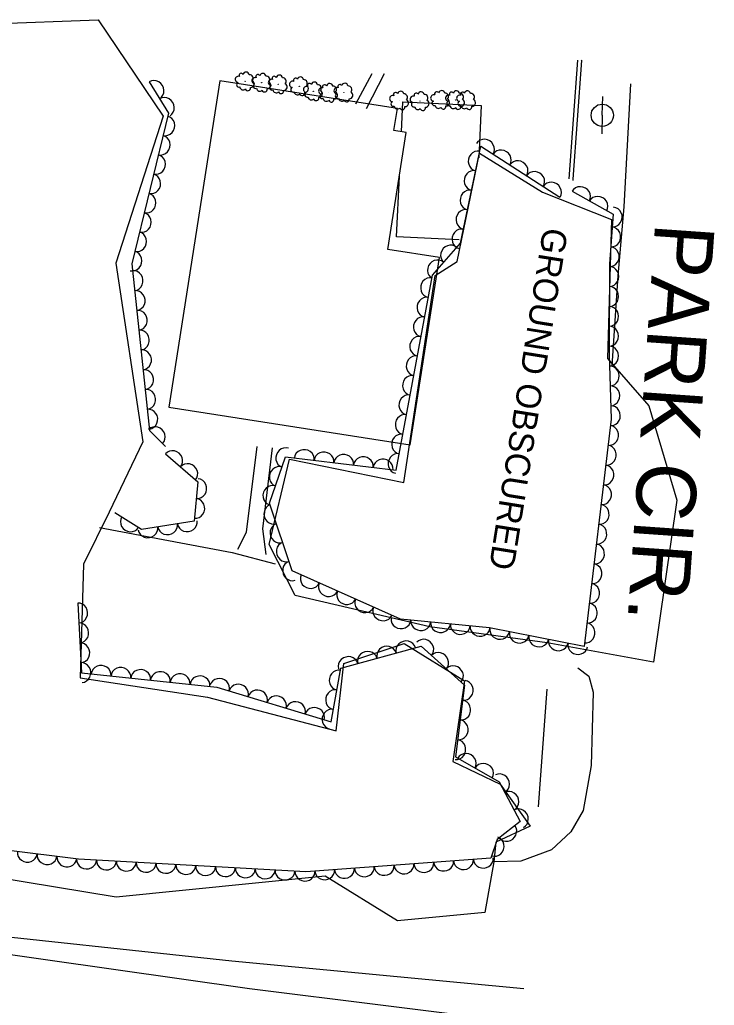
# Model space of a CAD drawing. Extents: x 1722896 to 1754269, y 648279 to 666297.
# Drawn here: x 1725117.8 to 1725257.5, y 658648.9 to 658847.2 of the extents above; entities that cross this region are included whole.
import ezdxf

# ---------------------------------------------------------------- set-up
doc = ezdxf.new("R2010")
doc.units = 0
for name, color, linetype in [('DESIGN - CENTERLINE - Proposed Text', 7, 'Continuous'), ('DESIGN - SHEET - Linework', 7, 'Continuous'), ('SURVEY - CENTERLINE - Preliminary', 7, 'Continuous'), ('SURVEY - CENTERLINE - Preliminary Text', 7, 'Continuous'), ('SURVEY - DTM - Breaklines', 7, 'Continuous'), ('SURVEY - VEGETATION - Features with Text', 7, 'Continuous')]:
    doc.layers.add(name, color=color, linetype=linetype)

msp = doc.modelspace()

# ---------------------------------------------------------------- linework, layer by layer
at = {"layer": 'DESIGN - CENTERLINE - Proposed Text'}
for points in [[(1725229.98, 658839.02), (1725228.27, 658815.18)], [(1725230.8, 658838.94), (1725229.09, 658815.1)], [(1725230.76, 658838.94), (1725230.81, 658839.01)], [(1725230.81, 658839.01), (1725230.8, 658838.94)], [(1725185.38, 658830.26), (1725188.67, 658836.35)], [(1725187.56, 658829.3), (1725191.15, 658836.34)], [(1725194.59, 658824.63), (1725194.88, 658830.65), (1725210.64, 658829.88), (1725210.13, 658819.39)], [(1725206.17, 658802.85), (1725193.55, 658803.47), (1725194.15, 658815.67)], [(1725229.09, 658815.1), (1725229.07, 658814.78)], [(1725161.62, 658740.64), (1725163.4, 658744.08), (1725165.56, 658761.33)], [(1725167.35, 658739.54), (1725166.68, 658744.73), (1725168.6, 658761.05)]]:
    msp.add_lwpolyline(points, dxfattribs=at)
msp.add_lwpolyline([(1725158, 658834.87), (1725147.74, 658769.2), (1725196.31, 658761.6), (1725202.2, 658799.32), (1725191.85, 658800.94), (1725195.53, 658824.49), (1725193.06, 658824.87), (1725193.75, 658829.28)], close=True, dxfattribs=at)
at = {"layer": 'SURVEY - CENTERLINE - Preliminary'}
for points in [[(1725111.82, 658846.36), (1725133.57, 658847.16), (1725146.63, 658827.76), (1725137.09, 658798.19), (1725142.5, 658762.21), (1725135.77, 658748.1), (1725130.6, 658737.62), (1725129.93, 658714.73), (1725155.55, 658710.84), (1725181.46, 658704.07), (1725182.96, 658717.62), (1725195.12, 658721.67), (1725207.28, 658714.18), (1725204.92, 658697.92), (1725214.43, 658693.35)], [(1725210.29, 658820.28), (1725222.98, 658812.44), (1725236.82, 658806.95), (1725236.04, 658778.97), (1725244.35, 658769.51), (1725249.96, 658750.49), (1725245.31, 658717.93), (1725223.89, 658721.79), (1725200.31, 658725), (1725173.17, 658731.31), (1725167.97, 658741.56), (1725172.06, 658758.72), (1725195.05, 658754.06), (1725201.37, 658795.7), (1725205.79, 658798.51), (1725210.29, 658820.28)], [(1725214.43, 658693.35), (1725220.49, 658684.94), (1725213.59, 658681.71), (1725213.18, 658677.77), (1725211.34, 658667.52), (1725193.77, 658665.88), (1725179.24, 658674.83), (1725137.19, 658670.6), (1725112.71, 658674.62)]]:
    msp.add_lwpolyline(points, dxfattribs=at)
at = {"layer": 'SURVEY - CENTERLINE - Preliminary Text'}
for points in [[(1725240.69, 658834.23), (1725239.33, 658809.49), (1725238.11, 658795.64), (1725236.92, 658777.55)], [(1725133.84, 658744.99), (1725160.51, 658739.96), (1725169.16, 658737.69)], [(1725230.1, 658716.75), (1725232.28, 658715.06), (1725233.14, 658711.9), (1725232.73, 658697.1), (1725231.11, 658688.08), (1725228.64, 658683.77), (1725224.75, 658680.18), (1725218.58, 658677.88), (1725213.18, 658677.77)], [(1725219.21, 658652.2), (1725160.44, 658657.78), (1725101.71, 658664.08), (1725041.61, 658671.16), (1725000.01, 658674.94), (1724971.97, 658677.19)], [(1725000.01, 658674.94), (1725035.79, 658669.37), (1725077.62, 658663.58), (1725109.21, 658660.02), (1725163.97, 658652.27), (1725217.78, 658645.58)]]:
    msp.add_lwpolyline(points, dxfattribs=at)
at = {"layer": 'SURVEY - DTM - Breaklines'}
for q in [(1725235.09, 658831.68), (1725234.9, 658824.18)]:
    msp.add_line((1725234.99, 658827.93), q, dxfattribs=at)
msp.add_circle((1725234.99, 658827.93), 2.25, dxfattribs=at)
at = {"layer": 'SURVEY - VEGETATION - Features with Text'}
for points in [[(1725143.81, 658834.65), (1725147.68, 658828.36), (1725140.32, 658798.03), (1725143.89, 658764.51), (1725147.1, 658761.32)], [(1725228.92, 658812.64), (1725237.15, 658808.03), (1725236.42, 658798.02), (1725236.38, 658779.8), (1725236.76, 658766.83), (1725231.31, 658721.09), (1725212.28, 658724.8), (1725194.41, 658726.54), (1725172.56, 658736.27), (1725168.05, 658749.91), (1725171.25, 658759.24), (1725193.52, 658756.54), (1725200.8, 658795.79), (1725206.46, 658802.21), (1725210.53, 658821.71), (1725226.46, 658811.48)], [(1725147.09, 658759.82), (1725153.62, 658754.19), (1725152.87, 658746.28), (1725142.27, 658744.63), (1725136.92, 658747.98)], [(1725129.42, 658729.79), (1725130.18, 658715.79), (1725157.44, 658712.9), (1725180.4, 658705.88), (1725182.38, 658716.73), (1725198.53, 658721.12), (1725207.25, 658713.31), (1725205.45, 658698.88), (1725214.22, 658693.86), (1725218.48, 658685.88), (1725213.81, 658682.2), (1725212.54, 658678.47), (1725175.33, 658675.74), (1725129.59, 658678.29), (1725100.41, 658681.89), (1725079.83, 658690.36), (1725046.88, 658695.34), (1725023.57, 658703), (1725006.03, 658707.8), (1725000.3, 658699.63), (1724944.71, 658706.84), (1724923.46, 658711.67), (1724891.95, 658713.84), (1724888, 658725.66)], [(1725223.84, 658712.46), (1725222.06, 658688.83)]]:
    msp.add_lwpolyline(points, dxfattribs=at)
for centre in [(1725163.11, 658834.76), (1725166.46, 658834.5), (1725169.78, 658834.16), (1725174.03, 658833.77), (1725176.85, 658832.74), (1725179.9, 658832.46), (1725182.98, 658832.49), (1725194.19, 658830.9), (1725198.3, 658830.78), (1725202.44, 658831.04), (1725205.43, 658830.99), (1725207.66, 658830.98)]:
    msp.add_circle(centre, 0.022, dxfattribs=at)
for centre, radius, start, end in [((1725161.75, 658835.15), 0.629, 70.277, 263.6967), ((1725162.34, 658835.95), 0.433, 30.2563, 209.002), ((1725163.32, 658836), 0.631, 8.1402, 164.9291), ((1725164.01, 658835.38), 0.719, 317.1929, 94.7171), ((1725165.1, 658834.88), 0.629, 70.277, 263.6967), ((1725165.69, 658835.69), 0.433, 30.2563, 209.002), ((1725166.68, 658835.74), 0.631, 8.1402, 164.9291), ((1725167.36, 658835.12), 0.719, 317.1929, 94.7171), ((1725169, 658835.35), 0.433, 30.2563, 209.002), ((1725169.99, 658835.4), 0.631, 8.1402, 164.9291), ((1725170.67, 658834.78), 0.719, 317.1929, 94.7171), ((1725174.24, 658835.01), 0.631, 8.1402, 164.9291), ((1725161.87, 658834.08), 0.479, 112.8957, 290.2148), ((1725162.7, 658833.73), 0.679, 188.1827, 315.0284), ((1725163.68, 658833.41), 0.527, 198.3416, 13.3419), ((1725164.22, 658834.25), 0.714, 268.0887, 63.9272), ((1725165.22, 658833.82), 0.479, 112.8957, 290.2148), ((1725167.57, 658833.99), 0.714, 268.0887, 63.9272), ((1725168.41, 658834.55), 0.629, 70.277, 263.6967), ((1725168.53, 658833.48), 0.479, 112.8957, 290.2148), ((1725170.88, 658833.65), 0.714, 268.0887, 63.9272), ((1725172.67, 658834.16), 0.629, 70.277, 263.6967), ((1725172.78, 658833.09), 0.479, 112.8957, 290.2148), ((1725173.26, 658834.96), 0.433, 30.2563, 209.002), ((1725175.48, 658833.13), 0.629, 70.277, 263.6967), ((1725174.92, 658834.39), 0.719, 317.1929, 94.7171), ((1725175.14, 658833.26), 0.714, 268.0887, 63.9272), ((1725176.08, 658833.93), 0.433, 30.2563, 209.002), ((1725177.06, 658833.99), 0.631, 8.1402, 164.9291), ((1725177.74, 658833.36), 0.719, 317.1929, 94.7171), ((1725179.12, 658833.65), 0.433, 30.2563, 209.002), ((1725180.11, 658833.7), 0.631, 8.1402, 164.9291), ((1725180.79, 658833.08), 0.719, 317.1929, 94.7171), ((1725181.62, 658832.88), 0.629, 70.277, 263.6967), ((1725182.21, 658833.68), 0.433, 30.2563, 209.002), ((1725183.19, 658833.74), 0.631, 8.1402, 164.9291), ((1725183.88, 658833.11), 0.719, 317.1929, 94.7171), ((1725166.06, 658833.46), 0.679, 188.1827, 315.0284), ((1725167.04, 658833.15), 0.527, 198.3416, 13.3419), ((1725169.37, 658833.13), 0.679, 188.1827, 315.0284), ((1725170.35, 658832.81), 0.527, 198.3416, 13.3419), ((1725173.62, 658832.74), 0.679, 188.1827, 315.0284), ((1725174.6, 658832.42), 0.527, 198.3416, 13.3419), ((1725175.6, 658832.06), 0.479, 112.8957, 290.2148), ((1725176.44, 658831.71), 0.679, 188.1827, 315.0284), ((1725177.42, 658831.4), 0.527, 198.3416, 13.3419), ((1725178.53, 658832.84), 0.629, 70.277, 263.6967), ((1725177.95, 658832.23), 0.714, 268.0887, 63.9272), ((1725178.65, 658831.78), 0.479, 112.8957, 290.2148), ((1725181, 658831.95), 0.714, 268.0887, 63.9272), ((1725181.74, 658831.81), 0.479, 112.8957, 290.2148), ((1725184.09, 658831.98), 0.714, 268.0887, 63.9272), ((1725192.82, 658831.29), 0.629, 70.277, 263.6967), ((1725193.41, 658832.09), 0.433, 30.2563, 209.002), ((1725194.4, 658832.14), 0.631, 8.1402, 164.9291), ((1725195.08, 658831.52), 0.719, 317.1929, 94.7171), ((1725196.94, 658831.17), 0.629, 70.277, 263.6967), ((1725197.53, 658831.97), 0.433, 30.2563, 209.002), ((1725198.51, 658832.02), 0.631, 8.1402, 164.9291), ((1725199.2, 658831.4), 0.719, 317.1929, 94.7171), ((1725201.08, 658831.43), 0.629, 70.277, 263.6967), ((1725201.67, 658832.23), 0.433, 30.2563, 209.002), ((1725202.65, 658832.28), 0.631, 8.1402, 164.9291), ((1725203.34, 658831.66), 0.719, 317.1929, 94.7171), ((1725204.07, 658831.37), 0.629, 70.277, 263.6967), ((1725204.66, 658832.18), 0.433, 30.2563, 209.002), ((1725205.64, 658832.23), 0.631, 8.1402, 164.9291), ((1725206.3, 658831.36), 0.629, 70.277, 263.6967), ((1725206.32, 658831.61), 0.719, 317.1929, 94.7171), ((1725206.89, 658832.16), 0.433, 30.2563, 209.002), ((1725207.87, 658832.22), 0.631, 8.1402, 164.9291), ((1725208.55, 658831.59), 0.719, 317.1929, 94.7171), ((1725179.49, 658831.42), 0.679, 188.1827, 315.0284), ((1725180.47, 658831.11), 0.527, 198.3416, 13.3419), ((1725182.57, 658831.46), 0.679, 188.1827, 315.0284), ((1725183.55, 658831.15), 0.527, 198.3416, 13.3419), ((1725192.94, 658830.22), 0.479, 112.8957, 290.2148), ((1725193.78, 658829.87), 0.679, 188.1827, 315.0284), ((1725194.76, 658829.55), 0.527, 198.3416, 13.3419), ((1725195.29, 658830.39), 0.714, 268.0887, 63.9272), ((1725197.06, 658830.1), 0.479, 112.8957, 290.2148), ((1725197.89, 658829.75), 0.679, 188.1827, 315.0284), ((1725198.87, 658829.43), 0.527, 198.3416, 13.3419), ((1725199.41, 658830.27), 0.714, 268.0887, 63.9272), ((1725201.2, 658830.36), 0.479, 112.8957, 290.2148), ((1725202.03, 658830.01), 0.679, 188.1827, 315.0284), ((1725203.01, 658829.69), 0.527, 198.3416, 13.3419), ((1725203.55, 658830.53), 0.714, 268.0887, 63.9272), ((1725204.18, 658830.31), 0.479, 112.8957, 290.2148), ((1725205.02, 658829.95), 0.679, 188.1827, 315.0284), ((1725206, 658829.64), 0.527, 198.3416, 13.3419), ((1725206.41, 658830.3), 0.479, 112.8957, 290.2148), ((1725206.54, 658830.48), 0.714, 268.0887, 63.9272), ((1725207.25, 658829.94), 0.679, 188.1827, 315.0284), ((1725208.23, 658829.63), 0.527, 198.3416, 13.3419), ((1725208.77, 658830.46), 0.714, 268.0887, 63.9272)]:
    msp.add_arc(centre, radius, start, end, dxfattribs=at)
for centre, major_axis in [((1725144.86, 658832.95), (1.05, -1.7)), ((1725146.95, 658829.54), (1.05, -1.7)), ((1725147.06, 658825.82), (-0.47, -1.94)), ((1725146.12, 658821.93), (-0.47, -1.94)), ((1725211.33, 658821.19), (1.68, -1.08)), ((1725145.18, 658818.05), (-0.47, -1.94)), ((1725209.91, 658818.73), (0.41, 1.96)), ((1725214.7, 658819.03), (1.68, -1.08)), ((1725218.07, 658816.87), (1.68, -1.08)), ((1725144.23, 658814.16), (-0.47, -1.94)), ((1725209.09, 658814.81), (0.41, 1.96)), ((1725221.43, 658814.7), (1.68, -1.08)), ((1725224.8, 658812.54), (1.68, -1.08)), ((1725230.66, 658811.66), (1.74, -0.98)), ((1725143.29, 658810.27), (-0.47, -1.94)), ((1725208.27, 658810.9), (0.41, 1.96)), ((1725234.15, 658809.71), (1.74, -0.98)), ((1725142.35, 658806.38), (-0.47, -1.94)), ((1725207.45, 658806.98), (0.41, 1.96)), ((1725237.11, 658807.46), (-0.15, -1.99)), ((1725141.4, 658802.5), (-0.47, -1.94)), ((1725206.64, 658803.06), (0.41, 1.96)), ((1725236.81, 658803.47), (-0.15, -1.99)), ((1725204.39, 658799.86), (1.32, 1.5)), ((1725140.46, 658798.61), (-0.47, -1.94)), ((1725236.52, 658799.48), (-0.15, -1.99)), ((1725201.74, 658796.87), (1.32, 1.5)), ((1725140.68, 658794.65), (0.21, -1.99)), ((1725236.41, 658795.49), (0, -2)), ((1725200.33, 658793.27), (0.36, 1.97)), ((1725141.11, 658790.67), (0.21, -1.99)), ((1725236.4, 658791.49), (0, -2)), ((1725199.6, 658789.33), (0.36, 1.97)), ((1725141.53, 658786.69), (0.21, -1.99)), ((1725236.39, 658787.49), (0, -2)), ((1725198.87, 658785.4), (0.36, 1.97)), ((1725141.95, 658782.71), (0.21, -1.99)), ((1725236.38, 658783.49), (0, -2)), ((1725198.14, 658781.47), (0.36, 1.97)), ((1725142.38, 658778.74), (0.21, -1.99)), ((1725236.38, 658779.49), (0.06, -2)), ((1725197.41, 658777.53), (0.36, 1.97)), ((1725142.8, 658774.76), (0.21, -1.99)), ((1725236.5, 658775.49), (0.06, -2)), ((1725196.68, 658773.6), (0.36, 1.97)), ((1725143.22, 658770.78), (0.21, -1.99)), ((1725236.62, 658771.49), (0.06, -2)), ((1725195.96, 658769.67), (0.36, 1.97)), ((1725143.65, 658766.8), (0.21, -1.99)), ((1725236.74, 658767.49), (0.06, -2)), ((1725195.23, 658765.73), (0.36, 1.97)), ((1725145.09, 658763.32), (1.42, -1.41)), ((1725236.37, 658763.52), (-0.24, -1.99)), ((1725194.5, 658761.8), (0.36, 1.97)), ((1725148.6, 658758.52), (1.51, -1.31)), ((1725171.18, 658759.04), (0.65, 1.89)), ((1725175.01, 658758.78), (1.99, -0.24)), ((1725178.98, 658758.3), (1.99, -0.24)), ((1725235.89, 658759.55), (-0.24, -1.99)), ((1725182.95, 658757.82), (1.99, -0.24)), ((1725186.92, 658757.34), (1.99, -0.24)), ((1725190.89, 658756.86), (1.99, -0.24)), ((1725193.77, 658757.87), (0.36, 1.97)), ((1725151.63, 658755.9), (1.51, -1.31)), ((1725169.88, 658755.26), (0.65, 1.89)), ((1725235.42, 658755.57), (-0.24, -1.99)), ((1725153.49, 658752.82), (-0.19, -1.99)), ((1725168.58, 658751.47), (0.65, 1.89)), ((1725234.95, 658751.6), (-0.24, -1.99)), ((1725153.11, 658748.84), (-0.19, -1.99)), ((1725168.79, 658747.68), (-0.63, 1.9)), ((1725234.47, 658747.63), (-0.24, -1.99)), ((1725139.98, 658746.06), (-1.69, 1.06)), ((1725151.46, 658746.06), (-1.98, -0.31)), ((1725143.55, 658744.83), (-1.98, -0.31)), ((1725147.51, 658745.44), (-1.98, -0.31)), ((1725170.04, 658743.88), (-0.63, 1.9)), ((1725234, 658743.66), (-0.24, -1.99)), ((1725171.3, 658740.09), (-0.63, 1.9)), ((1725233.53, 658739.69), (-0.24, -1.99)), ((1725172.56, 658736.29), (-0.63, 1.9)), ((1725233.05, 658735.71), (-0.24, -1.99)), ((1725176.2, 658734.65), (-1.83, 0.81)), ((1725179.85, 658733.02), (-1.83, 0.81)), ((1725232.58, 658731.74), (-0.24, -1.99)), ((1725183.51, 658731.4), (-1.83, 0.81)), ((1725187.16, 658729.77), (-1.83, 0.81)), ((1725129.53, 658727.79), (0.11, -2)), ((1725190.81, 658728.14), (-1.83, 0.81)), ((1725232.1, 658727.77), (-0.24, -1.99)), ((1725194.47, 658726.53), (-1.99, 0.19)), ((1725129.75, 658723.8), (0.11, -2)), ((1725198.46, 658726.15), (-1.99, 0.19)), ((1725202.44, 658725.76), (-1.99, 0.19)), ((1725206.42, 658725.37), (-1.99, 0.19)), ((1725210.4, 658724.98), (-1.99, 0.19)), ((1725214.35, 658724.4), (-1.96, 0.38)), ((1725231.63, 658723.8), (-0.24, -1.99)), ((1725199.13, 658720.58), (1.49, -1.33)), ((1725218.28, 658723.63), (-1.96, 0.38)), ((1725222.2, 658722.87), (-1.96, 0.38)), ((1725226.13, 658722.1), (-1.96, 0.38)), ((1725129.96, 658719.8), (0.11, -2)), ((1725191.58, 658719.23), (1.93, 0.53)), ((1725195.44, 658720.28), (1.93, 0.53)), ((1725230.06, 658721.34), (-1.96, 0.38)), ((1725183.86, 658717.13), (1.93, 0.53)), ((1725187.72, 658718.18), (1.93, 0.53)), ((1725202.11, 658717.92), (1.49, -1.33)), ((1725130.18, 658715.81), (0.11, -2)), ((1725134.14, 658715.37), (1.99, -0.21)), ((1725138.12, 658714.95), (1.99, -0.21)), ((1725142.09, 658714.53), (1.99, -0.21)), ((1725205.09, 658715.25), (1.49, -1.33)), ((1725146.07, 658714.11), (1.99, -0.21)), ((1725150.05, 658713.68), (1.99, -0.21)), ((1725154.03, 658713.26), (1.99, -0.21)), ((1725157.98, 658712.74), (1.91, -0.58)), ((1725181.94, 658714.3), (0.36, 1.97)), ((1725161.81, 658711.57), (1.91, -0.58)), ((1725207.12, 658712.23), (-0.25, -1.98)), ((1725165.63, 658710.4), (1.91, -0.58)), ((1725169.46, 658709.23), (1.91, -0.58)), ((1725181.22, 658710.37), (0.36, 1.97)), ((1725173.28, 658708.06), (1.91, -0.58)), ((1725177.11, 658706.89), (1.91, -0.58)), ((1725180.5, 658706.43), (0.36, 1.97)), ((1725206.62, 658708.26), (-0.25, -1.98)), ((1725206.12, 658704.29), (-0.25, -1.98)), ((1725205.63, 658700.32), (-0.25, -1.98)), ((1725207.65, 658697.61), (1.74, -0.99)), ((1725211.12, 658695.63), (1.74, -0.99)), ((1725214.42, 658693.47), (0.94, -1.76)), ((1725216.31, 658689.94), (0.94, -1.76)), ((1725218.2, 658686.42), (0.94, -1.76)), ((1725215.82, 658683.79), (-1.57, -1.24)), ((1725213.34, 658680.84), (-0.64, -1.89)), ((1725119.29, 658679.56), (-1.98, 0.24)), ((1725123.26, 658679.07), (-1.98, 0.24)), ((1725127.23, 658678.58), (-1.98, 0.24)), ((1725131.21, 658678.2), (-2, 0.11)), ((1725135.21, 658677.98), (-2, 0.11)), ((1725139.2, 658677.76), (-2, 0.11)), ((1725143.19, 658677.53), (-2, 0.11)), ((1725147.19, 658677.31), (-2, 0.11)), ((1725151.18, 658677.09), (-2, 0.11)), ((1725155.18, 658676.87), (-2, 0.11)), ((1725191.1, 658676.9), (-1.99, -0.15)), ((1725195.09, 658677.19), (-1.99, -0.15)), ((1725199.08, 658677.48), (-1.99, -0.15)), ((1725203.07, 658677.77), (-1.99, -0.15)), ((1725207.06, 658678.06), (-1.99, -0.15)), ((1725211.05, 658678.36), (-1.99, -0.15)), ((1725159.17, 658676.64), (-2, 0.11)), ((1725163.16, 658676.42), (-2, 0.11)), ((1725167.16, 658676.2), (-2, 0.11)), ((1725171.15, 658675.98), (-2, 0.11)), ((1725175.14, 658675.75), (-2, 0.11)), ((1725179.13, 658676.02), (-1.99, -0.15)), ((1725183.12, 658676.31), (-1.99, -0.15)), ((1725187.11, 658676.61), (-1.99, -0.15))]:
    msp.add_ellipse(centre, major_axis=major_axis, ratio=0.940188, start_param=0, end_param=3.141593, dxfattribs=at)

# ---------------------------------------------------------------- texts
at = {"layer": 'DESIGN - SHEET - Linework'}
msp.add_text('PARK CIR.', height=12, rotation=266.0154, dxfattribs=at).set_placement((1725245.65, 658806.44))
at = {"layer": 'SURVEY - CENTERLINE - Preliminary'}
msp.add_text('GROUND OBSCURED', height=5, rotation=260.9072, dxfattribs=at).set_placement((1725223.14, 658805.52))

doc.saveas('drawing.dxf')
